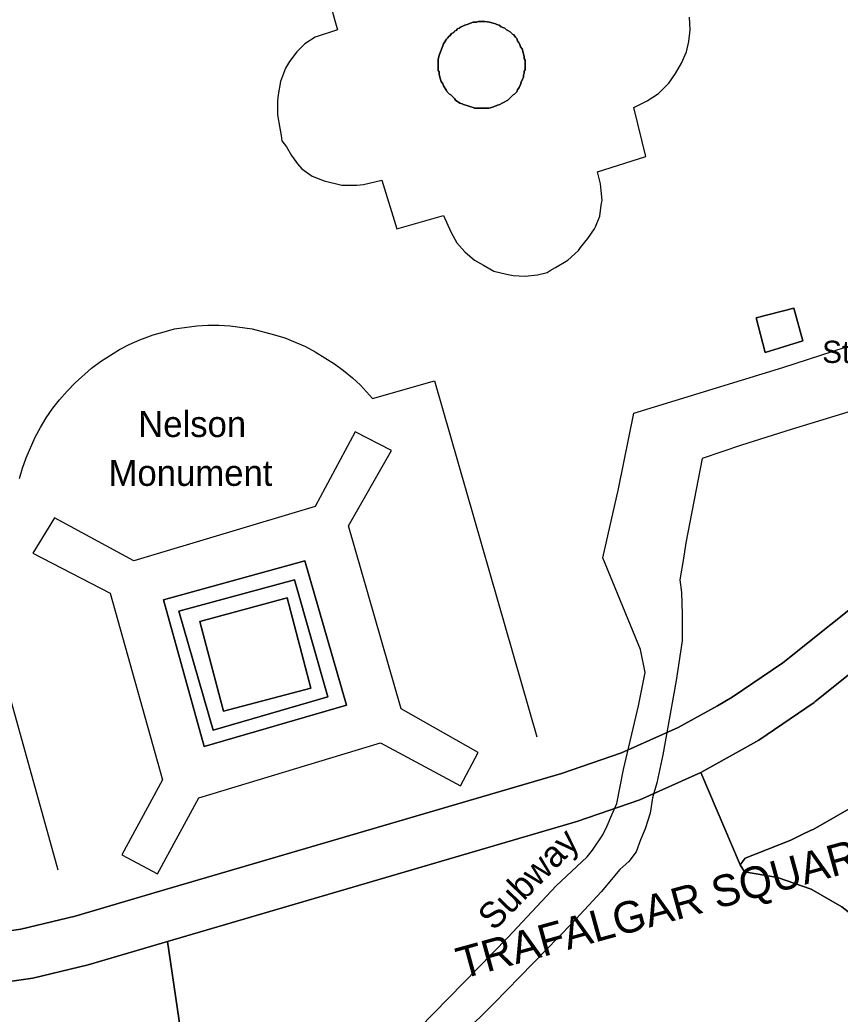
# Model space of a CAD drawing. Extents: x 529240 to 530363, y 179600 to 180767.
# Drawn here: x 530000.9 to 530056.2, y 180395.2 to 180462.3 of the extents above; entities that cross this region are included whole.
import ezdxf

# ---------------------------------------------------------------- set-up
doc = ezdxf.new("R2010")
doc.units = 0
for name, color, linetype in [('General surface', 7, 'Continuous'), ('Inland water', 7, 'Continuous'), ('Road Or Track', 7, 'Continuous'), ('Roadside', 7, 'Continuous'), ('Structure', 7, 'Continuous'), ('Unclassified', 7, 'Continuous')]:
    doc.layers.add(name, color=color, linetype=linetype)

msp = doc.modelspace()

# ---------------------------------------------------------------- linework, layer by layer
at = {"layer": 'General surface'}
for points in [[(530021.3, 180465.15), (530022.3, 180461.65), (530020.8, 180461.15), (530020.1, 180460.7), (530019.55, 180460.15), (530019.05, 180459.5), (530018.8, 180459.05), (530018.45, 180458.15), (530018.3, 180457.25), (530018.25, 180456.85), (530018.25, 180455.9), (530018.4, 180455), (530018.5, 180454.5), (530018.55, 180454.15), (530018.85, 180453.75), (530019.2, 180453.15), (530019.6, 180452.6), (530019.9, 180452.25), (530020.6, 180451.75), (530021.4, 180451.45), (530022.6, 180451.15), (530023.6, 180451.15), (530024.05, 180451.2), (530025.3, 180451.5), (530026.3, 180448.2), (530029.45, 180449.1), (530029.95, 180448), (530030.35, 180447.25), (530030.9, 180446.65), (530031.55, 180446.1), (530032.15, 180445.75), (530032.85, 180445.35), (530033.7, 180445.15), (530034.15, 180445.05), (530034.95, 180445), (530035.8, 180445.1), (530036.45, 180445.25), (530036.65, 180445.4), (530037, 180445.6), (530037.85, 180446.1), (530038.55, 180446.75), (530038.7, 180446.95), (530039.2, 180447.55), (530039.65, 180448.2), (530039.7, 180448.35), (530040, 180449.05), (530040.1, 180449.8), (530040.15, 180450.15), (530040.1, 180450.8), (530040.05, 180451.25), (530039.85, 180452.05), (530043.1, 180453.1), (530042.3, 180456.4), (530043.2, 180456.85), (530043.95, 180457.35), (530044.65, 180458.05), (530045.1, 180458.7), (530045.5, 180459.4), (530045.85, 180460.15), (530046, 180460.85), (530046.1, 180461.65), (530046.05, 180462.5)], [(529967.34, 180408.07), (529968.42, 180405.55), (529969.21, 180404.28), (529970.41, 180403.02), (529970.95, 180402.64), (529972.61, 180401.96), (529973.61, 180401.75), (529981.4, 180400.88), (529989.33, 180400.4), (529993.15, 180400.32), (529993.96, 180400.3), (529997.57, 180400.45), (529999.52, 180400.73), (530000, 180400.79), (530000.94, 180400.92), (530004.59, 180401.8), (530010.32, 180403.48), (530037.41, 180411.44), (530041.45, 180412.83), (530045.29, 180414.53), (530047.93, 180416.01), (530048.93, 180416.58), (530052.35, 180418.91), (530058.82, 180424.09)]]:
    msp.add_lwpolyline(points, dxfattribs=at)
for points in [[(530051.15, 180439.85), (530053.7, 180440.65), (530053.1, 180442.85), (530050.55, 180442.2)], [(530010.15, 180404.65), (530012.95, 180409.8), (530025.2, 180413.5), (530030.6, 180410.6), (530031.8, 180412.85), (530026.6, 180415.8), (530023.05, 180428.15), (530025.95, 180433.25), (530023.5, 180434.5), (530020.8, 180429.45), (530008.55, 180425.8), (530003.2, 180428.7), (530001.75, 180426.3), (530006.95, 180423.6), (530010.5, 180411), (530007.75, 180405.95)]]:
    msp.add_lwpolyline(points, close=True, dxfattribs=at)
at = {"layer": 'Inland water'}
msp.add_lwpolyline([(530021.3, 180465.15), (530022.3, 180461.65), (530020.8, 180461.15), (530020.1, 180460.7), (530019.55, 180460.15), (530019.05, 180459.5), (530018.8, 180459.05), (530018.45, 180458.15), (530018.3, 180457.25), (530018.25, 180456.85), (530018.25, 180455.9), (530018.4, 180455), (530018.5, 180454.5), (530018.55, 180454.15), (530018.85, 180453.75), (530019.2, 180453.15), (530019.6, 180452.6), (530019.9, 180452.25), (530020.6, 180451.75), (530021.4, 180451.45), (530022.6, 180451.15), (530023.6, 180451.15), (530024.05, 180451.2), (530025.3, 180451.5), (530026.3, 180448.2), (530029.45, 180449.1), (530029.95, 180448), (530030.35, 180447.25), (530030.9, 180446.65), (530031.55, 180446.1), (530032.15, 180445.75), (530032.85, 180445.35), (530033.7, 180445.15), (530034.15, 180445.05), (530034.95, 180445), (530035.8, 180445.1), (530036.45, 180445.25), (530036.65, 180445.4), (530037, 180445.6), (530037.85, 180446.1), (530038.55, 180446.75), (530038.7, 180446.95), (530039.2, 180447.55), (530039.65, 180448.2), (530039.7, 180448.35), (530040, 180449.05), (530040.1, 180449.8), (530040.15, 180450.15), (530040.1, 180450.8), (530040.05, 180451.25), (530039.85, 180452.05), (530043.1, 180453.1), (530042.3, 180456.4), (530043.2, 180456.85), (530043.95, 180457.35), (530044.65, 180458.05), (530045.1, 180458.7), (530045.5, 180459.4), (530045.85, 180460.15), (530046, 180460.85), (530046.1, 180461.65), (530046.05, 180462.5)], dxfattribs=at)
msp.add_lwpolyline([(530029.45, 180460.7), (530029.65, 180461), (530029.75, 180461.1), (530029.8, 180461.2), (530029.9, 180461.25), (530030, 180461.4), (530030.15, 180461.45), (530030.2, 180461.55), (530030.3, 180461.6), (530030.4, 180461.7), (530030.5, 180461.75), (530030.65, 180461.85), (530030.8, 180461.9), (530030.9, 180461.95), (530031.05, 180462), (530031.15, 180462.05), (530031.45, 180462.15), (530031.7, 180462.15), (530031.8, 180462.2), (530032.25, 180462.2), (530032.55, 180462.15), (530032.8, 180462.1), (530032.95, 180462.05), (530033.05, 180462), (530033.2, 180461.95), (530033.35, 180461.85), (530033.45, 180461.8), (530033.6, 180461.75), (530033.7, 180461.65), (530033.8, 180461.6), (530033.95, 180461.5), (530034.1, 180461.35), (530034.2, 180461.3), (530034.3, 180461.15), (530034.4, 180461.05), (530034.45, 180460.9), (530034.5, 180460.8), (530034.6, 180460.65), (530034.65, 180460.5), (530034.75, 180460.35), (530034.8, 180460.2), (530034.85, 180460), (530034.9, 180459.85), (530034.9, 180459.7), (530034.95, 180459.6), (530034.95, 180458.95), (530034.9, 180458.85), (530034.9, 180458.7), (530034.85, 180458.6), (530034.85, 180458.45), (530034.8, 180458.35), (530034.7, 180458.1), (530034.65, 180457.95), (530034.55, 180457.75), (530034.45, 180457.6), (530034.4, 180457.45), (530034.25, 180457.3), (530034.15, 180457.25), (530033.8, 180456.9), (530033.7, 180456.85), (530033.55, 180456.75), (530033.4, 180456.7), (530033.25, 180456.6), (530033.1, 180456.55), (530033, 180456.5), (530032.7, 180456.4), (530032.5, 180456.35), (530031.55, 180456.35), (530031.45, 180456.4), (530031.3, 180456.45), (530031.1, 180456.5), (530030.8, 180456.6), (530030.7, 180456.65), (530030.55, 180456.7), (530030.25, 180456.9), (530030.2, 180457), (530029.95, 180457.25), (530029.85, 180457.3), (530029.7, 180457.45), (530029.65, 180457.55), (530029.45, 180457.85), (530029.4, 180458), (530029.3, 180458.15), (530029.2, 180458.45), (530029.15, 180458.65), (530029.15, 180458.8), (530029.1, 180458.9), (530029.1, 180459.65), (530029.15, 180459.9), (530029.2, 180460.05), (530029.25, 180460.15), (530029.35, 180460.45), (530029.4, 180460.55)], close=True, dxfattribs=at)
at = {"layer": 'Road Or Track'}
for points in [[(530067.12, 180442.36), (530067.39, 180440.47), (530068.09, 180435.55), (530068.24, 180434.49), (530068.13, 180432.1), (530067.59, 180429.76), (530066.66, 180427.56), (530065.34, 180425.55), (530063.69, 180423.81), (530061, 180421.48), (530054.52, 180416.29), (530054.45, 180416.23), (530050.73, 180413.69), (530049.6, 180413.05), (530046.81, 180411.49)], [(530061, 180421.48), (530054.52, 180416.29), (530054.45, 180416.23), (530050.73, 180413.69), (530049.6, 180413.05), (530046.81, 180411.49), (530049.46, 180405.27), (530049.81, 180405.72), (530052.88, 180406.92), (530053.65, 180407.31), (530054.25, 180407.61), (530054.39, 180407.66), (530058.82, 180410.2)], [(530049.46, 180405.27), (530049.81, 180405.72), (530052.88, 180406.92), (530053.65, 180407.31), (530054.25, 180407.61), (530054.39, 180407.66), (530058.82, 180410.2), (530062.98, 180412.58), (530074.81, 180420.15)], [(530056.33, 180402.43), (530054.25, 180403.62), (530051.99, 180404.41), (530049.75, 180404.79), (530049.46, 180405.27), (530046.81, 180411.49), (530042.7, 180409.66), (530038.44, 180408.2), (530010.83, 180400.08), (530011.94, 180392.6)], [(530046.81, 180411.49), (530042.7, 180409.66), (530038.44, 180408.2), (530010.83, 180400.08)], [(530064.72, 180396.29), (530064.16, 180396.33), (530062.62, 180397.53), (530060.18, 180399.43), (530056.33, 180402.43), (530054.25, 180403.62), (530051.99, 180404.41), (530049.75, 180404.79), (530049.46, 180405.27)], [(530011.94, 180392.6), (530010.83, 180400.08), (530005.47, 180398.51), (530001.74, 180397.61), (530000, 180397.36), (529997.88, 180397.06), (529993.99, 180396.9), (529993.08, 180396.92), (529989.19, 180397), (529981.11, 180397.49), (529973.06, 180398.39), (529971.61, 180398.7), (529969.67, 180399.49), (529967.94, 180400.68), (529960.36, 180398.03), (529960.2, 180397.67), (529959.26, 180397.81), (529957.55, 180398.06), (529954.48, 180398.5), (529953.23, 180394.13)], [(530010.83, 180400.08), (530005.47, 180398.51), (530001.74, 180397.61), (530000, 180397.36), (529997.88, 180397.06), (529993.99, 180396.9), (529993.08, 180396.92), (529989.19, 180397), (529981.11, 180397.49), (529973.06, 180398.39), (529971.61, 180398.7), (529969.67, 180399.49), (529967.94, 180400.68)]]:
    msp.add_lwpolyline(points, dxfattribs=at)
at = {"layer": 'Roadside'}
for points in [[(530058.82, 180424.09), (530052.35, 180418.91), (530048.93, 180416.58), (530047.93, 180416.01), (530045.29, 180414.53), (530041.45, 180412.83), (530037.41, 180411.44), (530010.32, 180403.48), (530004.59, 180401.8), (530000.94, 180400.92), (530000, 180400.79), (529999.52, 180400.73), (529997.57, 180400.45), (529993.96, 180400.3), (529993.15, 180400.32), (529989.33, 180400.4), (529981.4, 180400.88), (529973.61, 180401.75), (529972.61, 180401.96), (529970.95, 180402.64), (529970.41, 180403.02), (529969.21, 180404.28), (529968.42, 180405.55), (529967.34, 180408.07)], [(529967.94, 180400.68), (529969.67, 180399.49), (529971.61, 180398.7), (529973.06, 180398.39), (529981.11, 180397.49), (529989.19, 180397), (529993.08, 180396.92), (529993.99, 180396.9), (529997.88, 180397.06), (530000, 180397.36), (530001.74, 180397.61), (530005.47, 180398.51), (530010.83, 180400.08), (530038.44, 180408.2), (530042.7, 180409.66), (530046.81, 180411.49), (530049.6, 180413.05), (530050.73, 180413.69), (530054.45, 180416.23), (530054.52, 180416.29), (530061, 180421.48)]]:
    msp.add_lwpolyline(points, dxfattribs=at)
msp.add_lwpolyline([(530049.46, 180405.27), (530049.75, 180404.79), (530051.99, 180404.41), (530054.25, 180403.62), (530056.33, 180402.43), (530060.18, 180399.43), (530062.62, 180397.53), (530064.16, 180396.33), (530064.72, 180396.29), (530066.03, 180399.09), (530068.51, 180404.42), (530075.54, 180419.53), (530075.45, 180420.08), (530075.19, 180420.23), (530074.81, 180420.15), (530062.98, 180412.58), (530058.82, 180410.2), (530054.39, 180407.66), (530054.25, 180407.61), (530053.65, 180407.31), (530052.88, 180406.92), (530049.81, 180405.72)], close=True, dxfattribs=at)
at = {"layer": 'Structure'}
for points in [[(530029.45, 180460.7), (530029.4, 180460.55), (530029.35, 180460.45), (530029.25, 180460.15), (530029.2, 180460.05), (530029.15, 180459.9), (530029.1, 180459.65), (530029.1, 180458.9), (530029.15, 180458.8), (530029.15, 180458.65), (530029.2, 180458.45), (530029.3, 180458.15), (530029.4, 180458), (530029.45, 180457.85), (530029.65, 180457.55), (530029.7, 180457.45), (530029.85, 180457.3), (530029.95, 180457.25), (530030.2, 180457), (530030.25, 180456.9), (530030.55, 180456.7), (530030.7, 180456.65), (530030.8, 180456.6), (530031.1, 180456.5), (530031.3, 180456.45), (530031.45, 180456.4), (530031.55, 180456.35), (530032.5, 180456.35), (530032.7, 180456.4), (530033, 180456.5), (530033.1, 180456.55), (530033.25, 180456.6), (530033.4, 180456.7), (530033.55, 180456.75), (530033.7, 180456.85), (530033.8, 180456.9), (530034.15, 180457.25), (530034.25, 180457.3), (530034.4, 180457.45), (530034.45, 180457.6), (530034.55, 180457.75), (530034.65, 180457.95), (530034.7, 180458.1), (530034.8, 180458.35), (530034.85, 180458.45), (530034.85, 180458.6), (530034.9, 180458.7), (530034.9, 180458.85), (530034.95, 180458.95), (530034.95, 180459.6), (530034.9, 180459.7), (530034.9, 180459.85), (530034.85, 180460), (530034.8, 180460.2), (530034.75, 180460.35), (530034.65, 180460.5), (530034.6, 180460.65), (530034.5, 180460.8), (530034.45, 180460.9), (530034.4, 180461.05), (530034.3, 180461.15), (530034.2, 180461.3), (530034.1, 180461.35), (530033.95, 180461.5), (530033.8, 180461.6), (530033.7, 180461.65), (530033.6, 180461.75), (530033.45, 180461.8), (530033.35, 180461.85), (530033.2, 180461.95), (530033.05, 180462), (530032.95, 180462.05), (530032.8, 180462.1), (530032.55, 180462.15), (530032.25, 180462.2), (530031.8, 180462.2), (530031.7, 180462.15), (530031.45, 180462.15), (530031.15, 180462.05), (530031.05, 180462), (530030.9, 180461.95), (530030.8, 180461.9), (530030.65, 180461.85), (530030.5, 180461.75), (530030.4, 180461.7), (530030.3, 180461.6), (530030.2, 180461.55), (530030.15, 180461.45), (530030, 180461.4), (530029.9, 180461.25), (530029.8, 180461.2), (530029.75, 180461.1), (530029.65, 180461)], [(530053.7, 180440.65), (530053.1, 180442.85), (530050.55, 180442.2), (530051.15, 180439.85)], [(530010.15, 180404.65), (530012.95, 180409.8), (530025.2, 180413.5), (530030.6, 180410.6), (530031.8, 180412.85), (530026.6, 180415.8), (530023.05, 180428.15), (530025.95, 180433.25), (530023.5, 180434.5), (530020.8, 180429.45), (530008.55, 180425.8), (530003.2, 180428.7), (530001.75, 180426.3), (530006.95, 180423.6), (530010.5, 180411), (530007.75, 180405.95)], [(530013.3, 180413.25), (530010.55, 180423.15), (530020.1, 180425.8), (530022.9, 180416.05)], [(530013.3, 180413.25), (530022.9, 180416.05), (530020.1, 180425.8), (530010.55, 180423.15)], [(530021.65, 180416.6), (530013.9, 180414.35), (530011.6, 180422.4), (530019.4, 180424.5)], [(530021.65, 180416.6), (530019.4, 180424.5), (530011.6, 180422.4), (530013.9, 180414.35)], [(530020.5, 180417.2), (530018.9, 180423.3), (530013, 180421.7), (530014.6, 180415.65)], [(530020.5, 180417.2), (530014.6, 180415.65), (530013, 180421.7), (530018.9, 180423.3)]]:
    msp.add_lwpolyline(points, close=True, dxfattribs=at)
at = {"layer": 'Unclassified'}
for points in [[(530021.3, 180465.15), (530022.3, 180461.65), (530020.8, 180461.15), (530020.1, 180460.7), (530019.55, 180460.15), (530019.05, 180459.5), (530018.8, 180459.05), (530018.45, 180458.15), (530018.3, 180457.25), (530018.25, 180456.85), (530018.25, 180455.9), (530018.4, 180455), (530018.5, 180454.5), (530018.55, 180454.15)], [(530018.55, 180454.15), (530018.85, 180453.75), (530019.2, 180453.15), (530019.6, 180452.6), (530019.9, 180452.25), (530020.6, 180451.75), (530021.4, 180451.45), (530022.6, 180451.15), (530023.6, 180451.15), (530024.05, 180451.2), (530025.3, 180451.5), (530026.3, 180448.2), (530029.45, 180449.1), (530029.95, 180448), (530030.35, 180447.25), (530030.9, 180446.65), (530031.55, 180446.1), (530032.15, 180445.75), (530032.85, 180445.35), (530033.7, 180445.15), (530034.15, 180445.05), (530034.95, 180445), (530035.8, 180445.1), (530036.45, 180445.25), (530036.65, 180445.4), (530037, 180445.6), (530037.85, 180446.1), (530038.55, 180446.75), (530038.7, 180446.95), (530039.2, 180447.55), (530039.65, 180448.2), (530039.7, 180448.35), (530040, 180449.05), (530040.1, 180449.8), (530040.15, 180450.15), (530040.1, 180450.8), (530040.05, 180451.25), (530039.85, 180452.05), (530043.1, 180453.1), (530042.3, 180456.4), (530043.2, 180456.85), (530043.95, 180457.35), (530044.65, 180458.05), (530045.1, 180458.7), (530045.5, 180459.4), (530045.85, 180460.15), (530046, 180460.85), (530046.1, 180461.65), (530046.05, 180462.5)], [(530029.45, 180460.7), (530029.65, 180461), (530029.75, 180461.1), (530029.8, 180461.2), (530029.9, 180461.25), (530030, 180461.4), (530030.15, 180461.45), (530030.2, 180461.55), (530030.3, 180461.6), (530030.4, 180461.7), (530030.5, 180461.75), (530030.65, 180461.85), (530030.8, 180461.9), (530030.9, 180461.95), (530031.05, 180462), (530031.15, 180462.05), (530031.45, 180462.15), (530031.7, 180462.15), (530031.8, 180462.2), (530032.25, 180462.2), (530032.55, 180462.15), (530032.8, 180462.1), (530032.95, 180462.05), (530033.05, 180462), (530033.2, 180461.95), (530033.35, 180461.85), (530033.45, 180461.8), (530033.6, 180461.75), (530033.7, 180461.65), (530033.8, 180461.6), (530033.95, 180461.5), (530034.1, 180461.35), (530034.2, 180461.3), (530034.3, 180461.15), (530034.4, 180461.05), (530034.45, 180460.9), (530034.5, 180460.8), (530034.6, 180460.65), (530034.65, 180460.5), (530034.75, 180460.35), (530034.8, 180460.2), (530034.85, 180460), (530034.9, 180459.85), (530034.9, 180459.7), (530034.95, 180459.6), (530034.95, 180458.95), (530034.9, 180458.85), (530034.9, 180458.7), (530034.85, 180458.6), (530034.85, 180458.45), (530034.8, 180458.35), (530034.7, 180458.1), (530034.65, 180457.95), (530034.55, 180457.75), (530034.45, 180457.6), (530034.4, 180457.45), (530034.25, 180457.3), (530034.15, 180457.25), (530033.8, 180456.9), (530033.7, 180456.85), (530033.55, 180456.75), (530033.4, 180456.7), (530033.25, 180456.6), (530033.1, 180456.55), (530033, 180456.5), (530032.7, 180456.4), (530032.5, 180456.35), (530031.55, 180456.35), (530031.45, 180456.4), (530031.3, 180456.45), (530031.1, 180456.5), (530030.8, 180456.6), (530030.7, 180456.65), (530030.55, 180456.7), (530030.25, 180456.9), (530030.2, 180457), (530029.95, 180457.25), (530029.85, 180457.3), (530029.7, 180457.45), (530029.65, 180457.55), (530029.45, 180457.85), (530029.4, 180458), (530029.3, 180458.15), (530029.2, 180458.45), (530029.15, 180458.65), (530029.15, 180458.8), (530029.1, 180458.9), (530029.1, 180459.65), (530029.15, 180459.9), (530029.2, 180460.05), (530029.25, 180460.15), (530029.35, 180460.45), (530029.4, 180460.55), (530029.45, 180460.7)], [(530053.7, 180440.65), (530051.15, 180439.85), (530050.55, 180442.2), (530053.1, 180442.85), (530053.7, 180440.65)], [(530000.85, 180431.35), (530001.05, 180432.05), (530001.3, 180432.75), (530001.9, 180434.15), (530002.25, 180434.8), (530002.65, 180435.45), (530003.1, 180436.1), (530003.55, 180436.65), (530004.05, 180437.25), (530004.6, 180437.8), (530005.7, 180438.8), (530006.3, 180439.25), (530007.6, 180440.05), (530008.25, 180440.4), (530008.95, 180440.7), (530009.85, 180441.05), (530010.6, 180441.25), (530011.3, 180441.45), (530012.8, 180441.65), (530013.55, 180441.7), (530014.3, 180441.7), (530015.05, 180441.65), (530016.55, 180441.45), (530018.05, 180441.05), (530018.75, 180440.85), (530020.15, 180440.25), (530020.8, 180439.9), (530022.1, 180439.1), (530022.7, 180438.65), (530023.3, 180438.15), (530023.85, 180437.65), (530024.65, 180436.75), (530028.85, 180437.95), (530035.75, 180413.9)], [(530025.8, 180392.2), (530028.8, 180395.25), (530033.8, 180400.35), (530037.05, 180403.85), (530039.15, 180405.8), (530039.5, 180406.25), (530040.2, 180407.3), (530040.5, 180407.9), (530040.8, 180408.65), (530041.15, 180409.4), (530041.6, 180411.7), (530042.6, 180416), (530043.05, 180418.25), (530042.75, 180419.8), (530040.2, 180426), (530041.25, 180430.65), (530042.3, 180435.75), (530052.35, 180438.85), (530055.75, 180439.95), (530056.7, 180440.25)], [(530058, 180436.2), (530052.9, 180434.65), (530049.55, 180433.6), (530046.9, 180432.7), (530045.8, 180427), (530045.65, 180425.95), (530045.4, 180424.5), (530045.5, 180423.65), (530045.55, 180422.2), (530045.55, 180420.4), (530045.15, 180417.7), (530044.25, 180412.7), (530043.85, 180410.8), (530043.55, 180409.8), (530043.4, 180408.75), (530043.05, 180407.7), (530042.75, 180406.95), (530042.45, 180406.15), (530041.95, 180405.5), (530041.35, 180404.95), (530040.1, 180403.45), (530038.1, 180401.3), (530032.85, 180395.9), (530028.65, 180391.75)], [(530010.15, 180404.65), (530012.95, 180409.8), (530025.2, 180413.5), (530030.6, 180410.6), (530031.8, 180412.85), (530026.6, 180415.8), (530023.05, 180428.15), (530025.95, 180433.25), (530023.5, 180434.5), (530020.8, 180429.45), (530008.55, 180425.8), (530003.2, 180428.7), (530001.75, 180426.3), (530006.95, 180423.6), (530010.5, 180411), (530007.75, 180405.95), (530010.15, 180404.65)], [(530013.3, 180413.25), (530022.9, 180416.05), (530020.1, 180425.8), (530010.55, 180423.15), (530013.3, 180413.25)], [(529967.34, 180408.07), (529968.42, 180405.55), (529969.21, 180404.28), (529970.41, 180403.02), (529970.95, 180402.64), (529972.61, 180401.96), (529973.61, 180401.75), (529981.4, 180400.88), (529989.33, 180400.4), (529993.15, 180400.32), (529993.96, 180400.3), (529997.57, 180400.45), (529999.52, 180400.73), (530000, 180400.79), (530000.94, 180400.92), (530004.59, 180401.8), (530010.32, 180403.48), (530037.41, 180411.44), (530041.45, 180412.83), (530045.29, 180414.53), (530047.93, 180416.01), (530048.93, 180416.58), (530052.35, 180418.91), (530058.82, 180424.09)], [(530021.65, 180416.6), (530019.4, 180424.5), (530011.6, 180422.4), (530013.9, 180414.35), (530021.65, 180416.6)], [(530020.5, 180417.2), (530018.9, 180423.3), (530013, 180421.7), (530014.6, 180415.65), (530020.5, 180417.2)], [(530003.45, 180404.9), (530000, 180417.3)], [(530049.46, 180405.27), (530046.81, 180411.49)], [(530011.94, 180392.6), (530010.83, 180400.08)]]:
    msp.add_lwpolyline(points, dxfattribs=at)

# ---------------------------------------------------------------- texts
at = {"layer": 'Road Or Track'}
msp.add_text('TRAFALGAR SQUARE', height=2.125, rotation=15.4, dxfattribs=at).set_placement((530030.68, 180397.54))
at = {"layer": 'Roadside'}
msp.add_text('Subway', height=1.75, rotation=45.3, dxfattribs=at).set_placement((530032.85, 180400.75))
at = {"layer": 'Structure'}
for s, height, p in [('Statue', 1.5, (530055, 180439.15)), ('Nelson', 1.75, (530008.85, 180434.15)), ('Monument', 1.75, (530006.85, 180430.85))]:
    msp.add_text(s, height=height, dxfattribs=at).set_placement(p)

doc.saveas('drawing.dxf')
